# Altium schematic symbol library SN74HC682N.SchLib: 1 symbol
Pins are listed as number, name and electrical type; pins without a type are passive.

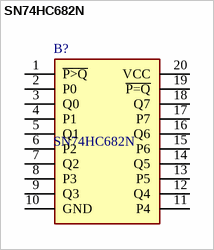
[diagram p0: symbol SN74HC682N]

## SN74HC682N
designator B?
Magnitude Comparator 8-Bit 20-Pin PDIP; Manufacturer_Name: Texas Instruments; Geometry.Height: 5.08mm
footprint DIP794W53P254L2540H508Q20N
pins: 1 ~{P>Q}, 2 P0, 3 Q0, 4 P1, 5 Q1, 6 P2, 7 Q2, 8 P3, 9 Q3, 10 GND, 11 P4, 12 Q4, 13 P5, 14 Q5, 15 P6, 16 Q6, 17 P7, 18 Q7, 19 ~{P=Q}, 20 VCC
